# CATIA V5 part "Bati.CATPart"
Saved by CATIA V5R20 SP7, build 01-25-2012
Part number: Bati
Bounding box of the stored display mesh (mm): x -15 to 15, y -23 to 63, z -7.5 to 12.954
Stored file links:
  U:\IAO_bon\Bati.CATPart
  U:\IAO_bon\Cqueguiner_IAo.CATProduct
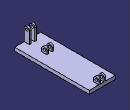
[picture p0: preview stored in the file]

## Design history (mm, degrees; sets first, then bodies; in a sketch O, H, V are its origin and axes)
Set1
  Point1 "Point A": linked copy from another document
  Point2 "Point E": linked copy from another document
  Point3 "Point D": linked copy from another document
Body1 (main body)
  Sketch1 on yz-plane, origin (0, 0, 0), H (0, 1, 0), V (0, 0, 1)
    line L1 (3, -3.5) -> (57, -3.5)
    line L2 (57, -3.5) -> (57, 0)
    point P3 (57, 0)
    arc A1 centre (60, 0) radius 3 from (57, 0) to (63, 0) cw
    point P4 (60, 0)
    line L3 (63, 0) -> (63, -7.5)
    line L4 (63, -7.5) -> (-23, -7.5)
    line L5 (-23, -7.5) -> (-23, 10)
    arc A2 centre (-20, 10) radius 3 from (-23, 10) to (-17, 10) cw
    point P9 (-20, 10)
    line L6 (-17, 10) -> (-17, -3.5)
    point P11 (-17, -3.5)
    line L7 (-17, -3.5) -> (-3, -3.5)
    line L8 (-3, -3.5) -> (-3, 0)
    point P13 (-3, 0)
    arc A3 centre (0, 0) radius 3 from (-3, 0) to (3, 0) cw
    point P14 (0, 0)
    line L9 (3, 0) -> (3, -3.5)
    reference projected point E1 (0, 0) from Point1
    reference projected point E2 (-20, 10) from Point2
    reference projected point E3 (60, 0) from Point3
    circle A4 centre (60, 0) radius 1.5
    circle A5 centre (0, 0) radius 1.5
    circle A6 centre (-20, 10) radius 1.5
    radius A1 = 3
    radius A3 = 3
    radius A2 = 3
    distance L1 L4 = 4
    radius A4 = 1.5
    radius A5 = 1.5
    radius A6 = 1.5
    length L8 = 3.5
    horizontal: L1 H, L4 H, L7 H
    coincidence: P3 H, P11 L1, P13 H, E1 P14, P9 E2, P4 E3, L7 L1
    vertical: L2 V, L5 V, L8 V
    tangency: A1 L2, L3 A1, A2 L5, L6 A2, A3 L8, L9 A3
  Pad1: profile Sketch1, direction (1, 0, 0), length 15, opposite side length 15
  Sketch2 on face of Pad1 from Sketch1.L1, origin (0, 0, -3.5), H (1, 0, 0), V (0, 1, 0)
    line L1 (4, 82) -> (52, 82)
    line L2 (52, 82) -> (52, -47)
    line L3 (52, -47) -> (4, -47)
    line L4 (4, -47) -> (4, 82)
    line L5 (-43, 82) -> (-4, 82)
    line L6 (-4, 82) -> (-4, -47)
    line L7 (-4, -47) -> (-43, -47)
    line L8 (-43, -47) -> (-43, 82)
    point P7 (-4, -47)
    line L9 (2, -51) -> (-2, -51)
    line L10 (-2, -51) -> (-2, 127)
    line L11 (-2, 127) -> (2, 127)
    line L12 (2, 127) -> (2, -51)
    distance L4 V = 4
    distance V L6 = 4
    distance L12 V = 2
    length L9 = 4
    horizontal: L1 H, L3 H, L5 H, L7 H, L9 H, L11 H
    vertical: L2 V, L4 V, L6 V, L8 V, L10 V, L12 V
    coincidence: P7 L3, L5 L1
  Pocket1: profile Sketch2, direction (0, 0, -1), length -50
